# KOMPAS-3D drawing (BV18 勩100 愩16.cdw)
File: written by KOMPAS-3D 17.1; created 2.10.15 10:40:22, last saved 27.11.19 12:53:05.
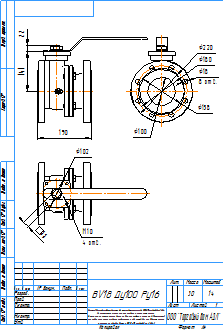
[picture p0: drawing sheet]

Sheet 1: A4, portrait

Title block, sheet 1: name: BV18 Ду100 Ру16; mass: 30; sheets: 1; sheet format: A4; stored path: C:\Users\kka\KOMPAS_Work\!Trash\BV18\KOMPAS 2D\BV18 Ду100 Ру16 с голым штоком.cdw

Views: Вид 1, Проекционный вид 2
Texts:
  Klimkovich
  ADL
  Рама для чертежей
  Лит-Масса-Масштаб
  Материал-Предприятие
  Масштаб
  Изм.
  Лист
  № докум.
  Подп.
  Дата
  Лит.
  Разраб.
  Пров.
  Т.контр.
  Листов
  Внимание! Данный продукт является объектом авторского права ООО «Торговый Дом АДЛ».
  Запрещается изменение, копирование, распространение
  (в том числе путем копирования на другие сайты и ресурсы в Интернете)
  или любое иное использование информации и объектов без предварительного
  согласия правообладателя (ООО «Торговый Дом АДЛ»).
  Н.контр.
  Утв.
  ООО "Торговый дом АДЛ"
  Изменение
  Номер документа
  Подпись
  Обозначение документа
  Наименование изделия
  Масса изделия по ГОСТ 2.109-73
  Порядковый номер листа
  Общее количество листов в документе
  Характер работы, выполненной лицом, подписавшим документ
  Наименование или индекс предприятия, выпускающего документ
  Инв. № подл.
  Подп. и дата
  Взам. инв. №
  Инв. № дубл.
  Инвентарный номер подлинника по ГОСТ 2.501-68
  Подпись принявшего подлинник в отдел технической документации
  Инвентарный номер подлинника, взамен которого выпущен данный подлинник
  Инвентарный номер дубликата по ГОСТ 2.502-68
  Подпись принявшего дубликат в отдел технической документации
  Справ. №
  Перв. примен.
  Обозначение документа, взамен или на основании которого выпущен данный документ
  Обозначение документа, в котором впервые записан данный документ
  Подпись лица, копировавшего чертеж
  Обозначение формата листа
  !Рама для чертежа
Dimensions and other numbers on the sheet: 220; 180; 158; 18; 8 отв.; 100; 190; 141; 22; 1:4; 1; 30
